(* Logix 5000 project; controller R21 vendor 1 type 14 code 96 rev 21.11; software revision 21.00; part 3 of 5 *)

ADD_ON_INSTRUCTION PSDNP3EventG21V06   (* revision 1.0, vendor ProSoft Technology Inc *)
VAR_IN_OUT
   EventBuffer : PSDNP3MasterEvent[1]; {required}
END_VAR
VAR_INPUT
   BufferSize : DINT; {required}
   CurrentBufferIndex : DINT; {required}
   Reset : BOOL; {required}
   OutstationNodeAddress : INT; {required}
   OutstationIPAddress0 : INT; {required}
   OutstationIPAddress1 : INT; {required}
   OutstationIPAddress2 : INT; {required}
   OutstationIPAddress3 : INT; {required}
END_VAR
VAR_IN_OUT
   DNP3StaticObject : PSDNP3FrozenCounter16WithFlagTime[1]; {required}
END_VAR
VAR_INPUT
   MaxtElementCount : DINT; {required}
END_VAR
VAR_OUTPUT
   EventsProcessed : DINT; {access Read Only, visible}
   LastElementIndex : DINT; {access Read Only, visible}
   LastValue : DINT; {access Read Only, visible}
   LastStatus : SINT; {access Read Only, visible}
   CurrentUnloadIndex : DINT; {access Read Only, visible}
END_VAR
VAR
   UnloadIndex : DINT; {access None}
   EnableInTemp : BOOL; {access None}
   InitialScan : BOOL; {access None}
   EntryValidForProcessing : BOOL; {access None}
   ElementIndex : DINT; {access None}
   NextIndex : DINT; {access None}
   ResetPulse : BOOL; {access None}
   ResetONS : BOOL; {access None}
END_VAR

ROUTINE Logic   (* ladder *)
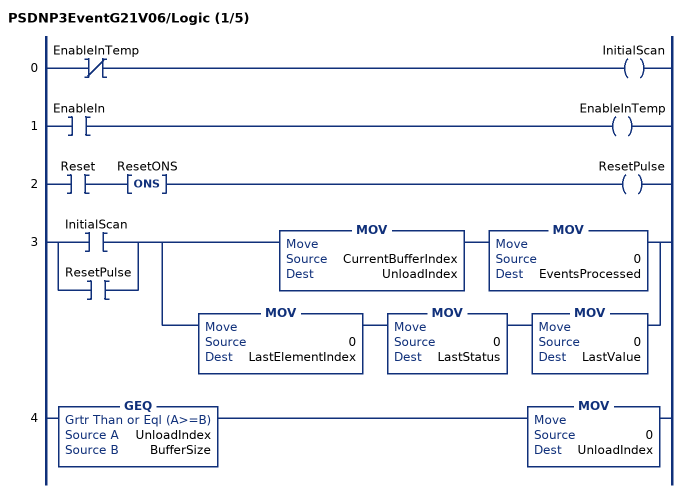
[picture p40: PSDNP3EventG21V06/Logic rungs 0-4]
   0: XIO(EnableInTemp)OTE(InitialScan);
   1: XIC(EnableIn)OTE(EnableInTemp);
   2: XIC(Reset)ONS(ResetONS)OTE(ResetPulse);
   3: [XIC(InitialScan) ,XIC(ResetPulse) ][MOV(CurrentBufferIndex,UnloadIndex) MOV(0,EventsProcessed) ,MOV(0,LastElementIndex) MOV(0,LastStatus) MOV(0,LastValue) ];
   4: GEQ(UnloadIndex,BufferSize)MOV(0,UnloadIndex);
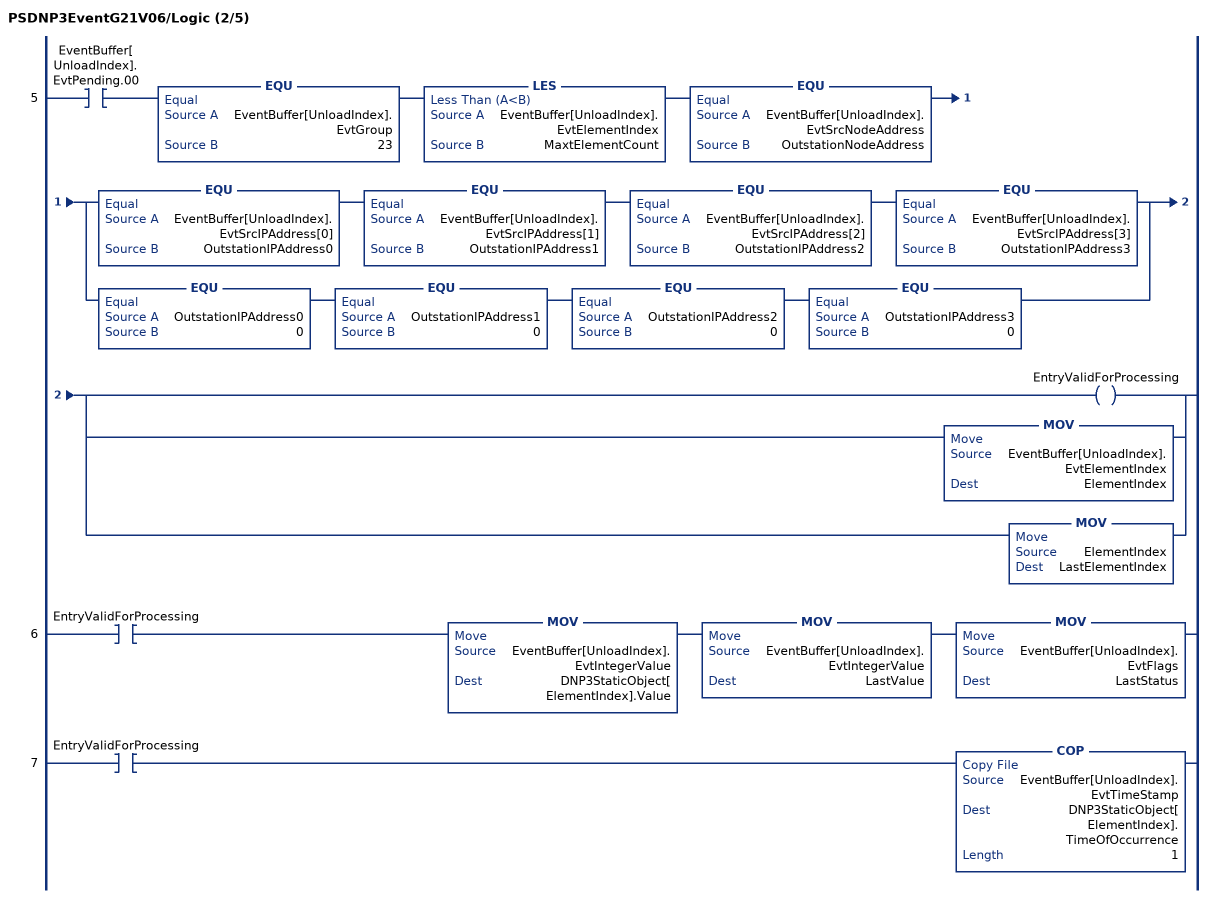
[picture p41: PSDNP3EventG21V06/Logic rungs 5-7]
   5: XIC(EventBuffer[UnloadIndex].EvtPending.00)EQU(EventBuffer[UnloadIndex].EvtGroup,23)LES(EventBuffer[UnloadIndex].EvtElementIndex,MaxtElementCount)EQU(EventBuffer[UnloadIndex].EvtSrcNodeAddress,OutstationNodeAddress)[EQU(EventBuffer[UnloadIndex].EvtSrcIPAddress[0],OutstationIPAddress0) EQU(EventBuffer[UnloadIndex].EvtSrcIPAddress[1],OutstationIPAddress1) EQU(EventBuffer[UnloadIndex].EvtSrcIPAddress[2],OutstationIPAddress2) EQU(EventBuffer[UnloadIndex].EvtSrcIPAddress[3],OutstationIPAddress3) ,EQU(OutstationIPAddress0,0) EQU(OutstationIPAddress1,0) EQU(OutstationIPAddress2,0) EQU(OutstationIPAddress3,0) ][OTE(EntryValidForProcessing) ,MOV(EventBuffer[UnloadIndex].EvtElementIndex,ElementIndex) ,MOV(ElementIndex,LastElementIndex) ];
   6: XIC(EntryValidForProcessing)MOV(EventBuffer[UnloadIndex].EvtIntegerValue,DNP3StaticObject[ElementIndex].Value)MOV(EventBuffer[UnloadIndex].EvtIntegerValue,LastValue)MOV(EventBuffer[UnloadIndex].EvtFlags,LastStatus);
   7: XIC(EntryValidForProcessing)COP(EventBuffer[UnloadIndex].EvtTimeStamp,DNP3StaticObject[ElementIndex].TimeOfOccurrence,1);
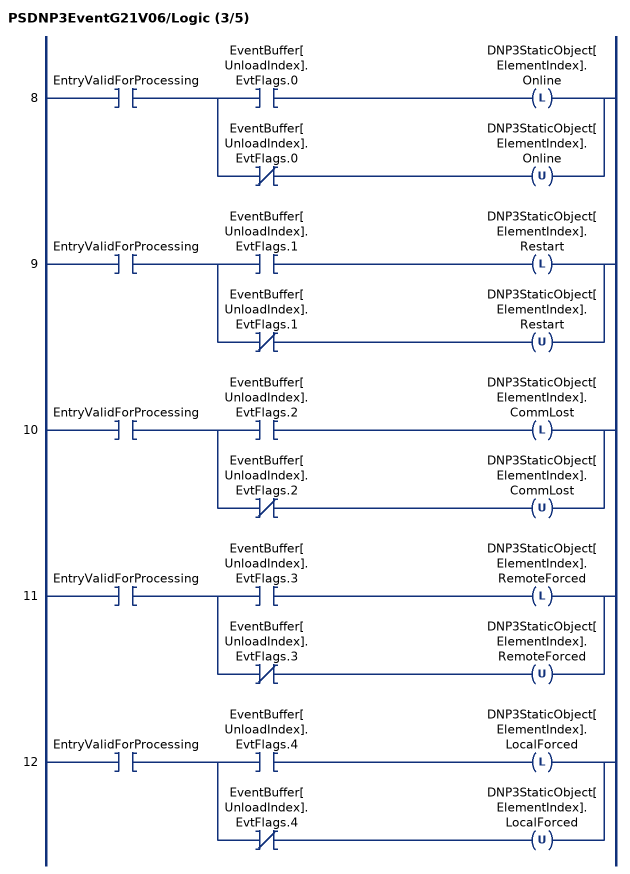
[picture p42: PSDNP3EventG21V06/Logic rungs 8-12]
   8: XIC(EntryValidForProcessing)[XIC(EventBuffer[UnloadIndex].EvtFlags.0) OTL(DNP3StaticObject[ElementIndex].Online) ,XIO(EventBuffer[UnloadIndex].EvtFlags.0) OTU(DNP3StaticObject[ElementIndex].Online) ];
   9: XIC(EntryValidForProcessing)[XIC(EventBuffer[UnloadIndex].EvtFlags.1) OTL(DNP3StaticObject[ElementIndex].Restart) ,XIO(EventBuffer[UnloadIndex].EvtFlags.1) OTU(DNP3StaticObject[ElementIndex].Restart) ];
   10: XIC(EntryValidForProcessing)[XIC(EventBuffer[UnloadIndex].EvtFlags.2) OTL(DNP3StaticObject[ElementIndex].CommLost) ,XIO(EventBuffer[UnloadIndex].EvtFlags.2) OTU(DNP3StaticObject[ElementIndex].CommLost) ];
   11: XIC(EntryValidForProcessing)[XIC(EventBuffer[UnloadIndex].EvtFlags.3) OTL(DNP3StaticObject[ElementIndex].RemoteForced) ,XIO(EventBuffer[UnloadIndex].EvtFlags.3) OTU(DNP3StaticObject[ElementIndex].RemoteForced) ];
   12: XIC(EntryValidForProcessing)[XIC(EventBuffer[UnloadIndex].EvtFlags.4) OTL(DNP3StaticObject[ElementIndex].LocalForced) ,XIO(EventBuffer[UnloadIndex].EvtFlags.4) OTU(DNP3StaticObject[ElementIndex].LocalForced) ];
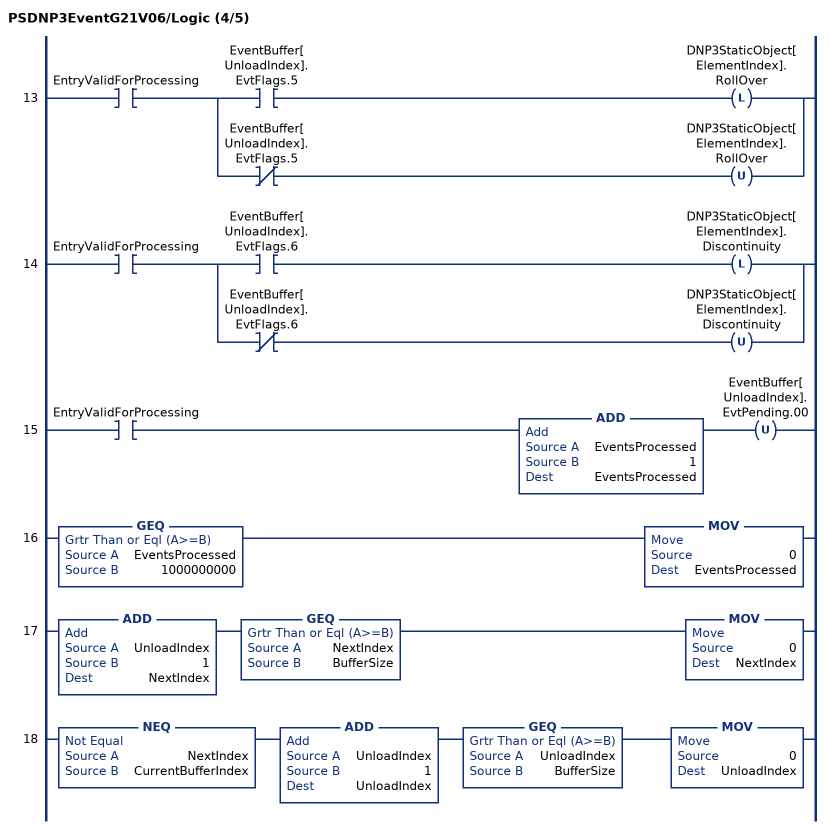
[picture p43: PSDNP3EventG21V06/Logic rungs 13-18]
   13: XIC(EntryValidForProcessing)[XIC(EventBuffer[UnloadIndex].EvtFlags.5) OTL(DNP3StaticObject[ElementIndex].RollOver) ,XIO(EventBuffer[UnloadIndex].EvtFlags.5) OTU(DNP3StaticObject[ElementIndex].RollOver) ];
   14: XIC(EntryValidForProcessing)[XIC(EventBuffer[UnloadIndex].EvtFlags.6) OTL(DNP3StaticObject[ElementIndex].Discontinuity) ,XIO(EventBuffer[UnloadIndex].EvtFlags.6) OTU(DNP3StaticObject[ElementIndex].Discontinuity) ];
   15: XIC(EntryValidForProcessing)ADD(EventsProcessed,1,EventsProcessed)OTU(EventBuffer[UnloadIndex].EvtPending.00);
   16: GEQ(EventsProcessed,1000000000)MOV(0,EventsProcessed);
   17: ADD(UnloadIndex,1,NextIndex)GEQ(NextIndex,BufferSize)MOV(0,NextIndex);
   18: NEQ(NextIndex,CurrentBufferIndex)ADD(UnloadIndex,1,UnloadIndex)GEQ(UnloadIndex,BufferSize)MOV(0,UnloadIndex);
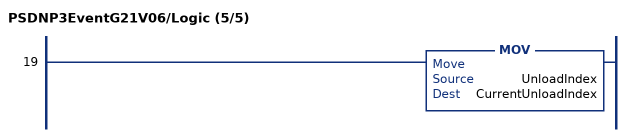
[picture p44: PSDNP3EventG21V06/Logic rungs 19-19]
   19: MOV(UnloadIndex,CurrentUnloadIndex);
END_ROUTINE
END_ADD_ON_INSTRUCTION

ADD_ON_INSTRUCTION PSDNP3EventG21V09   (* revision 1.0, vendor ProSoft Technology Inc *)
VAR_IN_OUT
   EventBuffer : PSDNP3MasterEvent[1]; {required}
END_VAR
VAR_INPUT
   BufferSize : DINT; {required}
   CurrentBufferIndex : DINT; {required}
   Reset : BOOL; {required}
   OutstationNodeAddress : INT; {required}
   OutstationIPAddress0 : INT; {required}
   OutstationIPAddress1 : INT; {required}
   OutstationIPAddress2 : INT; {required}
   OutstationIPAddress3 : INT; {required}
END_VAR
VAR_IN_OUT
   DNP3StaticObject : DINT[1]; {required}
END_VAR
VAR_INPUT
   MaxtElementCount : DINT; {required}
END_VAR
VAR_OUTPUT
   EventsProcessed : DINT; {access Read Only, visible}
   LastElementIndex : DINT; {access Read Only, visible}
   LastValue : DINT; {access Read Only, visible}
   LastStatus : SINT; {access Read Only, visible}
   CurrentUnloadIndex : DINT; {access Read Only, visible}
END_VAR
VAR
   UnloadIndex : DINT; {access None}
   EnableInTemp : BOOL; {access None}
   InitialScan : BOOL; {access None}
   EntryValidForProcessing : BOOL; {access None}
   ElementIndex : DINT; {access None}
   NextIndex : DINT; {access None}
   ResetPulse : BOOL; {access None}
   ResetONS : BOOL; {access None}
END_VAR

ROUTINE Logic   (* ladder *)
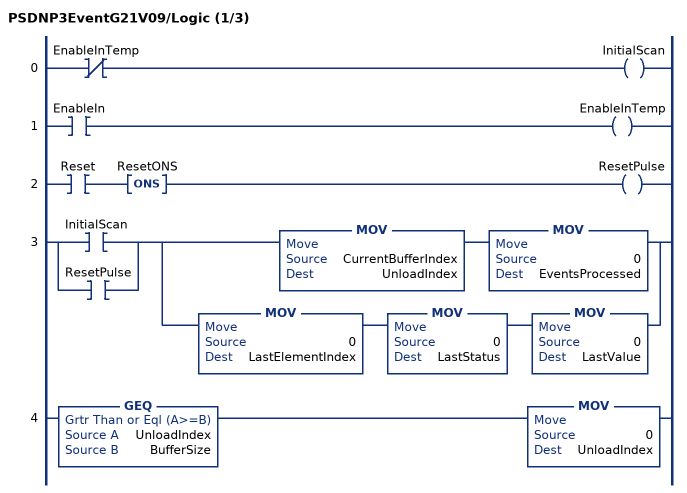
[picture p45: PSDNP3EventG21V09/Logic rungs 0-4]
   0: XIO(EnableInTemp)OTE(InitialScan);
   1: XIC(EnableIn)OTE(EnableInTemp);
   2: XIC(Reset)ONS(ResetONS)OTE(ResetPulse);
   3: [XIC(InitialScan) ,XIC(ResetPulse) ][MOV(CurrentBufferIndex,UnloadIndex) MOV(0,EventsProcessed) ,MOV(0,LastElementIndex) MOV(0,LastStatus) MOV(0,LastValue) ];
   4: GEQ(UnloadIndex,BufferSize)MOV(0,UnloadIndex);
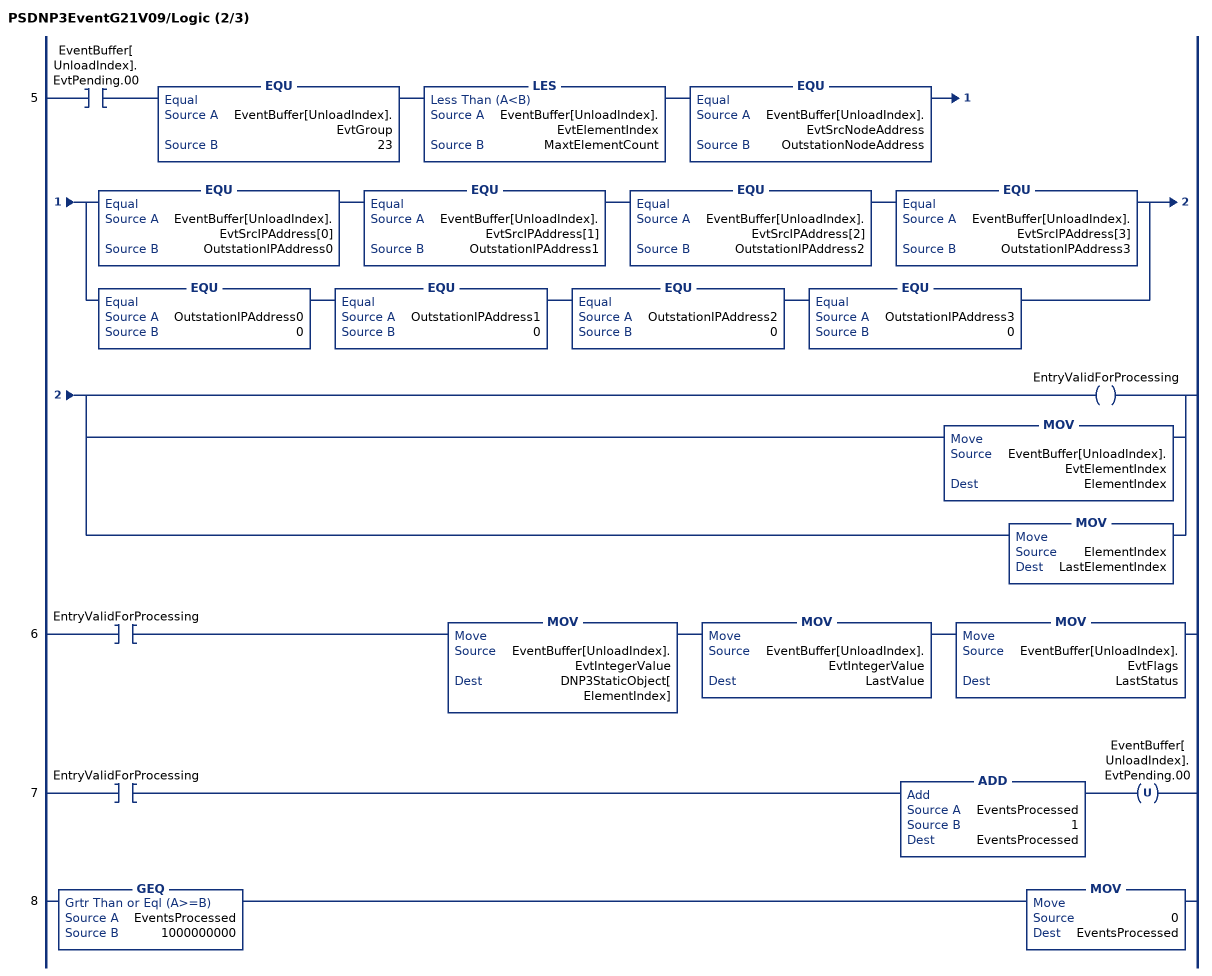
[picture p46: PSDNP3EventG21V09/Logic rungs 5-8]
   5: XIC(EventBuffer[UnloadIndex].EvtPending.00)EQU(EventBuffer[UnloadIndex].EvtGroup,23)LES(EventBuffer[UnloadIndex].EvtElementIndex,MaxtElementCount)EQU(EventBuffer[UnloadIndex].EvtSrcNodeAddress,OutstationNodeAddress)[EQU(EventBuffer[UnloadIndex].EvtSrcIPAddress[0],OutstationIPAddress0) EQU(EventBuffer[UnloadIndex].EvtSrcIPAddress[1],OutstationIPAddress1) EQU(EventBuffer[UnloadIndex].EvtSrcIPAddress[2],OutstationIPAddress2) EQU(EventBuffer[UnloadIndex].EvtSrcIPAddress[3],OutstationIPAddress3) ,EQU(OutstationIPAddress0,0) EQU(OutstationIPAddress1,0) EQU(OutstationIPAddress2,0) EQU(OutstationIPAddress3,0) ][OTE(EntryValidForProcessing) ,MOV(EventBuffer[UnloadIndex].EvtElementIndex,ElementIndex) ,MOV(ElementIndex,LastElementIndex) ];
   6: XIC(EntryValidForProcessing)MOV(EventBuffer[UnloadIndex].EvtIntegerValue,DNP3StaticObject[ElementIndex])MOV(EventBuffer[UnloadIndex].EvtIntegerValue,LastValue)MOV(EventBuffer[UnloadIndex].EvtFlags,LastStatus);
   7: XIC(EntryValidForProcessing)ADD(EventsProcessed,1,EventsProcessed)OTU(EventBuffer[UnloadIndex].EvtPending.00);
   8: GEQ(EventsProcessed,1000000000)MOV(0,EventsProcessed);
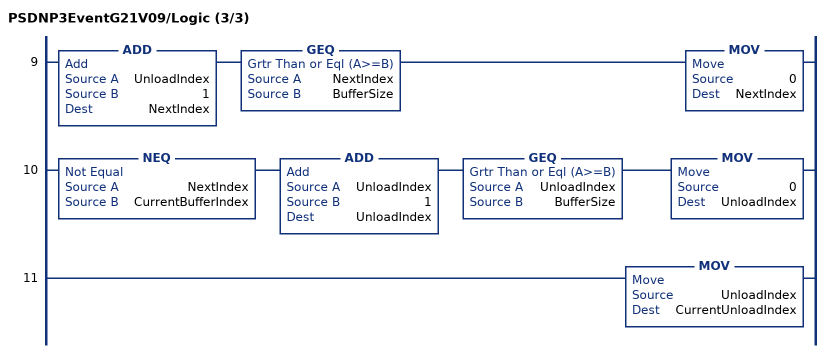
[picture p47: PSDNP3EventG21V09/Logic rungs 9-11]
   9: ADD(UnloadIndex,1,NextIndex)GEQ(NextIndex,BufferSize)MOV(0,NextIndex);
   10: NEQ(NextIndex,CurrentBufferIndex)ADD(UnloadIndex,1,UnloadIndex)GEQ(UnloadIndex,BufferSize)MOV(0,UnloadIndex);
   11: MOV(UnloadIndex,CurrentUnloadIndex);
END_ROUTINE
END_ADD_ON_INSTRUCTION

ADD_ON_INSTRUCTION PSDNP3EventG21V10   (* revision 1.0, vendor ProSoft Technology Inc *)
VAR_IN_OUT
   EventBuffer : PSDNP3MasterEvent[1]; {required}
END_VAR
VAR_INPUT
   BufferSize : DINT; {required}
   CurrentBufferIndex : DINT; {required}
   Reset : BOOL; {required}
   OutstationNodeAddress : INT; {required}
   OutstationIPAddress0 : INT; {required}
   OutstationIPAddress1 : INT; {required}
   OutstationIPAddress2 : INT; {required}
   OutstationIPAddress3 : INT; {required}
END_VAR
VAR_IN_OUT
   DNP3StaticObject : INT[1]; {required}
END_VAR
VAR_INPUT
   MaxtElementCount : DINT; {required}
END_VAR
VAR_OUTPUT
   EventsProcessed : DINT; {access Read Only, visible}
   LastElementIndex : DINT; {access Read Only, visible}
   LastValue : DINT; {access Read Only, visible}
   LastStatus : SINT; {access Read Only, visible}
   CurrentUnloadIndex : DINT; {access Read Only, visible}
END_VAR
VAR
   UnloadIndex : DINT; {access None}
   EnableInTemp : BOOL; {access None}
   InitialScan : BOOL; {access None}
   EntryValidForProcessing : BOOL; {access None}
   ElementIndex : DINT; {access None}
   NextIndex : DINT; {access None}
   ResetPulse : BOOL; {access None}
   ResetONS : BOOL; {access None}
END_VAR

ROUTINE Logic   (* ladder *)
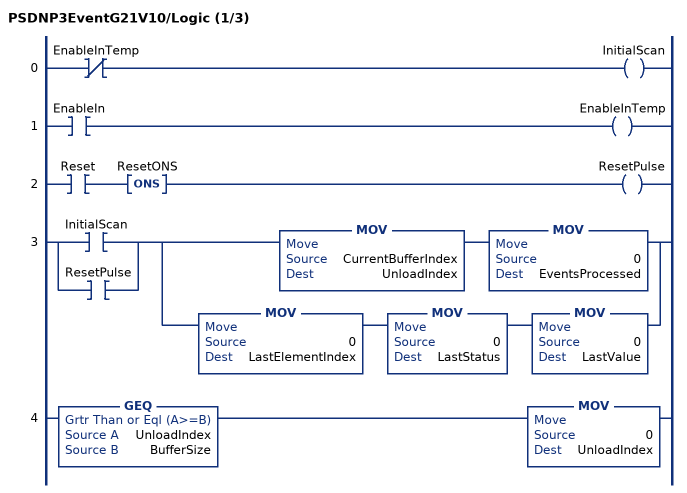
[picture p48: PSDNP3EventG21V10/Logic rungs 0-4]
   0: XIO(EnableInTemp)OTE(InitialScan);
   1: XIC(EnableIn)OTE(EnableInTemp);
   2: XIC(Reset)ONS(ResetONS)OTE(ResetPulse);
   3: [XIC(InitialScan) ,XIC(ResetPulse) ][MOV(CurrentBufferIndex,UnloadIndex) MOV(0,EventsProcessed) ,MOV(0,LastElementIndex) MOV(0,LastStatus) MOV(0,LastValue) ];
   4: GEQ(UnloadIndex,BufferSize)MOV(0,UnloadIndex);
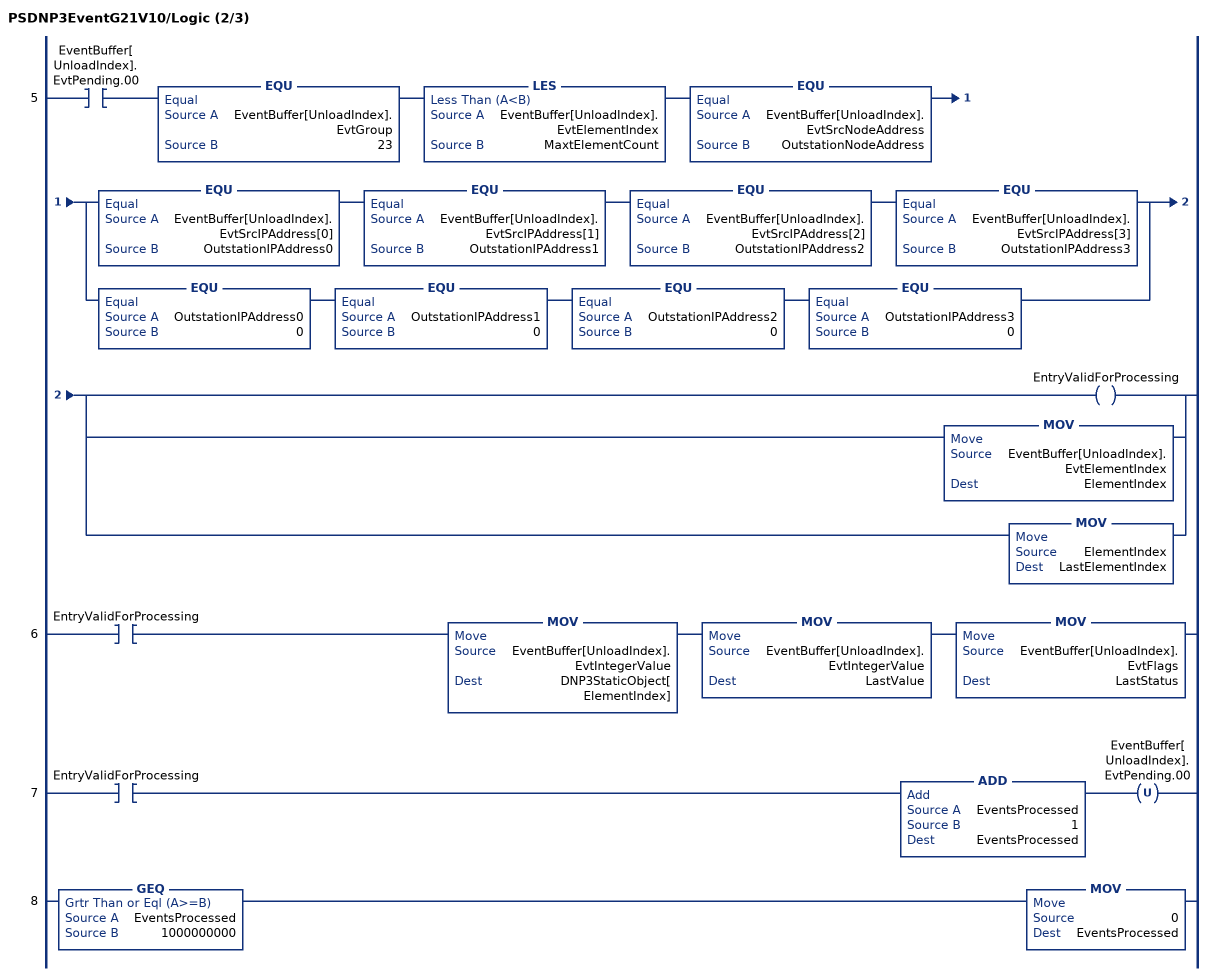
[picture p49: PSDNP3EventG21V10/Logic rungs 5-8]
   5: XIC(EventBuffer[UnloadIndex].EvtPending.00)EQU(EventBuffer[UnloadIndex].EvtGroup,23)LES(EventBuffer[UnloadIndex].EvtElementIndex,MaxtElementCount)EQU(EventBuffer[UnloadIndex].EvtSrcNodeAddress,OutstationNodeAddress)[EQU(EventBuffer[UnloadIndex].EvtSrcIPAddress[0],OutstationIPAddress0) EQU(EventBuffer[UnloadIndex].EvtSrcIPAddress[1],OutstationIPAddress1) EQU(EventBuffer[UnloadIndex].EvtSrcIPAddress[2],OutstationIPAddress2) EQU(EventBuffer[UnloadIndex].EvtSrcIPAddress[3],OutstationIPAddress3) ,EQU(OutstationIPAddress0,0) EQU(OutstationIPAddress1,0) EQU(OutstationIPAddress2,0) EQU(OutstationIPAddress3,0) ][OTE(EntryValidForProcessing) ,MOV(EventBuffer[UnloadIndex].EvtElementIndex,ElementIndex) ,MOV(ElementIndex,LastElementIndex) ];
   6: XIC(EntryValidForProcessing)MOV(EventBuffer[UnloadIndex].EvtIntegerValue,DNP3StaticObject[ElementIndex])MOV(EventBuffer[UnloadIndex].EvtIntegerValue,LastValue)MOV(EventBuffer[UnloadIndex].EvtFlags,LastStatus);
   7: XIC(EntryValidForProcessing)ADD(EventsProcessed,1,EventsProcessed)OTU(EventBuffer[UnloadIndex].EvtPending.00);
   8: GEQ(EventsProcessed,1000000000)MOV(0,EventsProcessed);
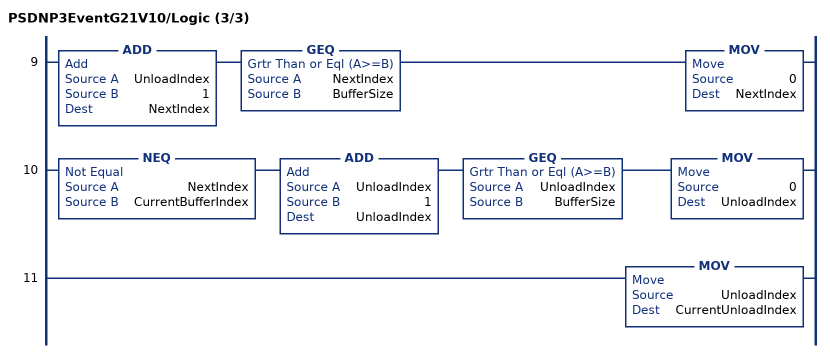
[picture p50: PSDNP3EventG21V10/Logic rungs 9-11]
   9: ADD(UnloadIndex,1,NextIndex)GEQ(NextIndex,BufferSize)MOV(0,NextIndex);
   10: NEQ(NextIndex,CurrentBufferIndex)ADD(UnloadIndex,1,UnloadIndex)GEQ(UnloadIndex,BufferSize)MOV(0,UnloadIndex);
   11: MOV(UnloadIndex,CurrentUnloadIndex);
END_ROUTINE
END_ADD_ON_INSTRUCTION

ADD_ON_INSTRUCTION PSDNP3EventG30V01   (* revision 1.0, vendor ProSoft Technology Inc *)
VAR_IN_OUT
   EventBuffer : PSDNP3MasterEvent[1]; {required}
END_VAR
VAR_INPUT
   BufferSize : DINT; {required}
   CurrentBufferIndex : DINT; {required}
   Reset : BOOL; {required}
   OutstationNodeAddress : INT; {required}
   OutstationIPAddress0 : INT; {required}
   OutstationIPAddress1 : INT; {required}
   OutstationIPAddress2 : INT; {required}
   OutstationIPAddress3 : INT; {required}
END_VAR
VAR_IN_OUT
   DNP3StaticObject : PSDNP3AnalogInput32Flag[1]; {required}
END_VAR
VAR_INPUT
   MaxtElementCount : DINT; {required}
END_VAR
VAR_OUTPUT
   EventsProcessed : DINT; {access Read Only, visible}
   LastElementIndex : DINT; {access Read Only, visible}
   LastValue : DINT; {access Read Only, visible}
   LastStatus : SINT; {access Read Only, visible}
   CurrentUnloadIndex : DINT; {access Read Only, visible}
END_VAR
VAR
   UnloadIndex : DINT; {access None}
   EnableInTemp : BOOL; {access None}
   InitialScan : BOOL; {access None}
   EntryValidForProcessing : BOOL; {access None}
   ElementIndex : DINT; {access None}
   NextIndex : DINT; {access None}
   ResetPulse : BOOL; {access None}
   ResetONS : BOOL; {access None}
END_VAR

ROUTINE Logic   (* ladder *)
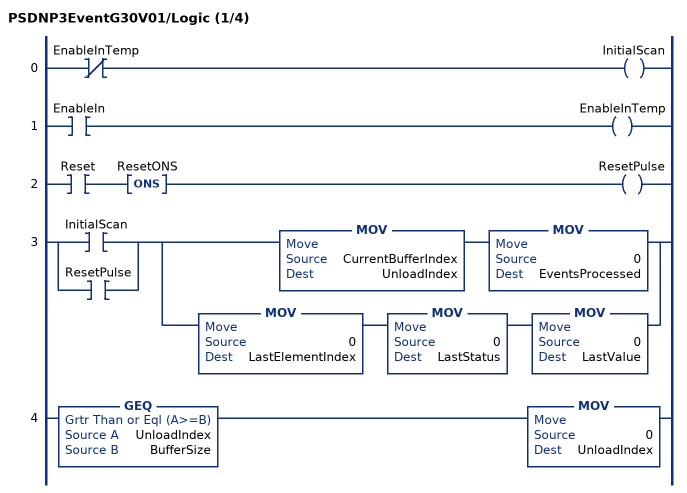
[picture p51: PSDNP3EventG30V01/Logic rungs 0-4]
   0: XIO(EnableInTemp)OTE(InitialScan);
   1: XIC(EnableIn)OTE(EnableInTemp);
   2: XIC(Reset)ONS(ResetONS)OTE(ResetPulse);
   3: [XIC(InitialScan) ,XIC(ResetPulse) ][MOV(CurrentBufferIndex,UnloadIndex) MOV(0,EventsProcessed) ,MOV(0,LastElementIndex) MOV(0,LastStatus) MOV(0,LastValue) ];
   4: GEQ(UnloadIndex,BufferSize)MOV(0,UnloadIndex);
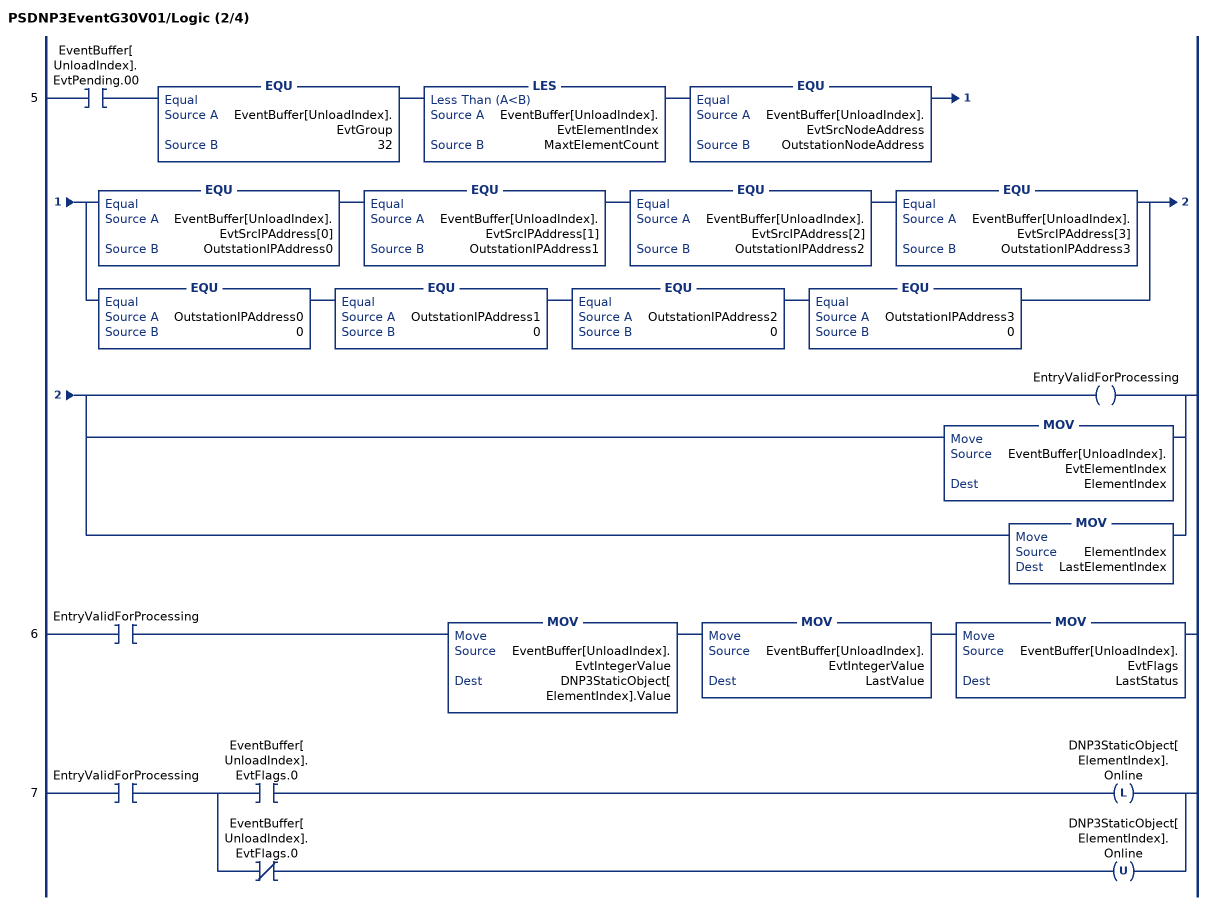
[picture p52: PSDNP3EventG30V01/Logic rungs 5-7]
   5: XIC(EventBuffer[UnloadIndex].EvtPending.00)EQU(EventBuffer[UnloadIndex].EvtGroup,32)LES(EventBuffer[UnloadIndex].EvtElementIndex,MaxtElementCount)EQU(EventBuffer[UnloadIndex].EvtSrcNodeAddress,OutstationNodeAddress)[EQU(EventBuffer[UnloadIndex].EvtSrcIPAddress[0],OutstationIPAddress0) EQU(EventBuffer[UnloadIndex].EvtSrcIPAddress[1],OutstationIPAddress1) EQU(EventBuffer[UnloadIndex].EvtSrcIPAddress[2],OutstationIPAddress2) EQU(EventBuffer[UnloadIndex].EvtSrcIPAddress[3],OutstationIPAddress3) ,EQU(OutstationIPAddress0,0) EQU(OutstationIPAddress1,0) EQU(OutstationIPAddress2,0) EQU(OutstationIPAddress3,0) ][OTE(EntryValidForProcessing) ,MOV(EventBuffer[UnloadIndex].EvtElementIndex,ElementIndex) ,MOV(ElementIndex,LastElementIndex) ];
   6: XIC(EntryValidForProcessing)MOV(EventBuffer[UnloadIndex].EvtIntegerValue,DNP3StaticObject[ElementIndex].Value)MOV(EventBuffer[UnloadIndex].EvtIntegerValue,LastValue)MOV(EventBuffer[UnloadIndex].EvtFlags,LastStatus);
   7: XIC(EntryValidForProcessing)[XIC(EventBuffer[UnloadIndex].EvtFlags.0) OTL(DNP3StaticObject[ElementIndex].Online) ,XIO(EventBuffer[UnloadIndex].EvtFlags.0) OTU(DNP3StaticObject[ElementIndex].Online) ];
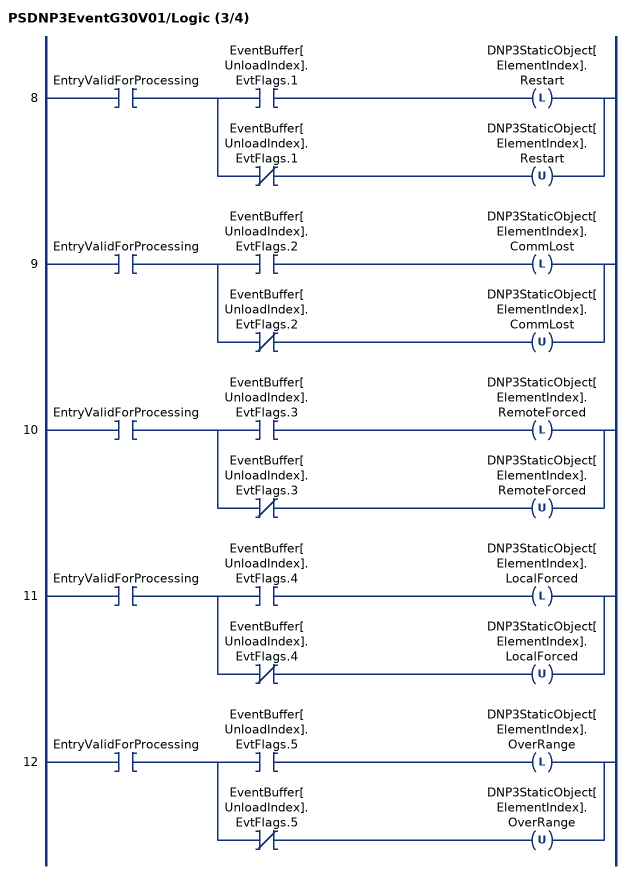
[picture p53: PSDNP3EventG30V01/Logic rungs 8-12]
   8: XIC(EntryValidForProcessing)[XIC(EventBuffer[UnloadIndex].EvtFlags.1) OTL(DNP3StaticObject[ElementIndex].Restart) ,XIO(EventBuffer[UnloadIndex].EvtFlags.1) OTU(DNP3StaticObject[ElementIndex].Restart) ];
   9: XIC(EntryValidForProcessing)[XIC(EventBuffer[UnloadIndex].EvtFlags.2) OTL(DNP3StaticObject[ElementIndex].CommLost) ,XIO(EventBuffer[UnloadIndex].EvtFlags.2) OTU(DNP3StaticObject[ElementIndex].CommLost) ];
   10: XIC(EntryValidForProcessing)[XIC(EventBuffer[UnloadIndex].EvtFlags.3) OTL(DNP3StaticObject[ElementIndex].RemoteForced) ,XIO(EventBuffer[UnloadIndex].EvtFlags.3) OTU(DNP3StaticObject[ElementIndex].RemoteForced) ];
   11: XIC(EntryValidForProcessing)[XIC(EventBuffer[UnloadIndex].EvtFlags.4) OTL(DNP3StaticObject[ElementIndex].LocalForced) ,XIO(EventBuffer[UnloadIndex].EvtFlags.4) OTU(DNP3StaticObject[ElementIndex].LocalForced) ];
   12: XIC(EntryValidForProcessing)[XIC(EventBuffer[UnloadIndex].EvtFlags.5) OTL(DNP3StaticObject[ElementIndex].OverRange) ,XIO(EventBuffer[UnloadIndex].EvtFlags.5) OTU(DNP3StaticObject[ElementIndex].OverRange) ];
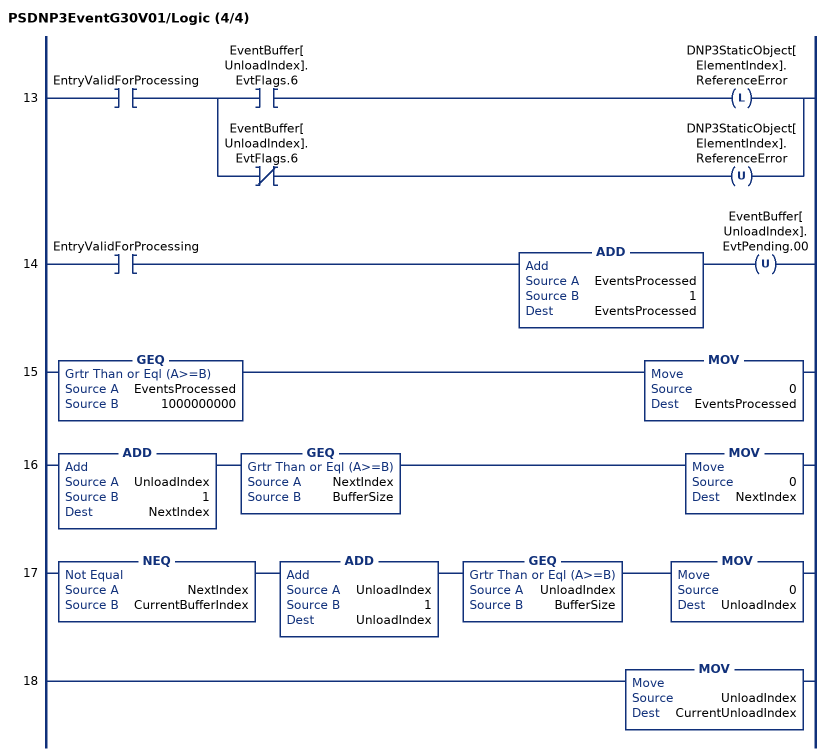
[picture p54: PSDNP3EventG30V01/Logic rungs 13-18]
   13: XIC(EntryValidForProcessing)[XIC(EventBuffer[UnloadIndex].EvtFlags.6) OTL(DNP3StaticObject[ElementIndex].ReferenceError) ,XIO(EventBuffer[UnloadIndex].EvtFlags.6) OTU(DNP3StaticObject[ElementIndex].ReferenceError) ];
   14: XIC(EntryValidForProcessing)ADD(EventsProcessed,1,EventsProcessed)OTU(EventBuffer[UnloadIndex].EvtPending.00);
   15: GEQ(EventsProcessed,1000000000)MOV(0,EventsProcessed);
   16: ADD(UnloadIndex,1,NextIndex)GEQ(NextIndex,BufferSize)MOV(0,NextIndex);
   17: NEQ(NextIndex,CurrentBufferIndex)ADD(UnloadIndex,1,UnloadIndex)GEQ(UnloadIndex,BufferSize)MOV(0,UnloadIndex);
   18: MOV(UnloadIndex,CurrentUnloadIndex);
END_ROUTINE
END_ADD_ON_INSTRUCTION

ADD_ON_INSTRUCTION PSDNP3EventG30V02   (* revision 1.0, vendor ProSoft Technology Inc *)
VAR_IN_OUT
   EventBuffer : PSDNP3MasterEvent[1]; {required}
END_VAR
VAR_INPUT
   BufferSize : DINT; {required}
   CurrentBufferIndex : DINT; {required}
   Reset : BOOL; {required}
   OutstationNodeAddress : INT; {required}
   OutstationIPAddress0 : INT; {required}
   OutstationIPAddress1 : INT; {required}
   OutstationIPAddress2 : INT; {required}
   OutstationIPAddress3 : INT; {required}
END_VAR
VAR_IN_OUT
   DNP3StaticObject : PSDNP3AnalogInput16Flag[1]; {required}
END_VAR
VAR_INPUT
   MaxtElementCount : DINT; {required}
END_VAR
VAR_OUTPUT
   EventsProcessed : DINT; {access Read Only, visible}
   LastElementIndex : DINT; {access Read Only, visible}
   LastValue : DINT; {access Read Only, visible}
   LastStatus : SINT; {access Read Only, visible}
   CurrentUnloadIndex : DINT; {access Read Only, visible}
END_VAR
VAR
   UnloadIndex : DINT; {access None}
   EnableInTemp : BOOL; {access None}
   InitialScan : BOOL; {access None}
   EntryValidForProcessing : BOOL; {access None}
   ElementIndex : DINT; {access None}
   NextIndex : DINT; {access None}
   ResetPulse : BOOL; {access None}
   ResetONS : BOOL; {access None}
END_VAR

ROUTINE Logic   (* ladder *)
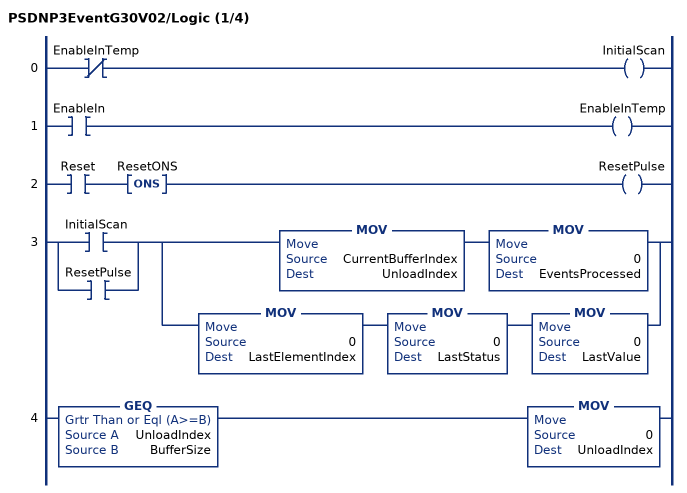
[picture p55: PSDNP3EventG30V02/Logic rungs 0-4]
   0: XIO(EnableInTemp)OTE(InitialScan);
   1: XIC(EnableIn)OTE(EnableInTemp);
   2: XIC(Reset)ONS(ResetONS)OTE(ResetPulse);
   3: [XIC(InitialScan) ,XIC(ResetPulse) ][MOV(CurrentBufferIndex,UnloadIndex) MOV(0,EventsProcessed) ,MOV(0,LastElementIndex) MOV(0,LastStatus) MOV(0,LastValue) ];
   4: GEQ(UnloadIndex,BufferSize)MOV(0,UnloadIndex);
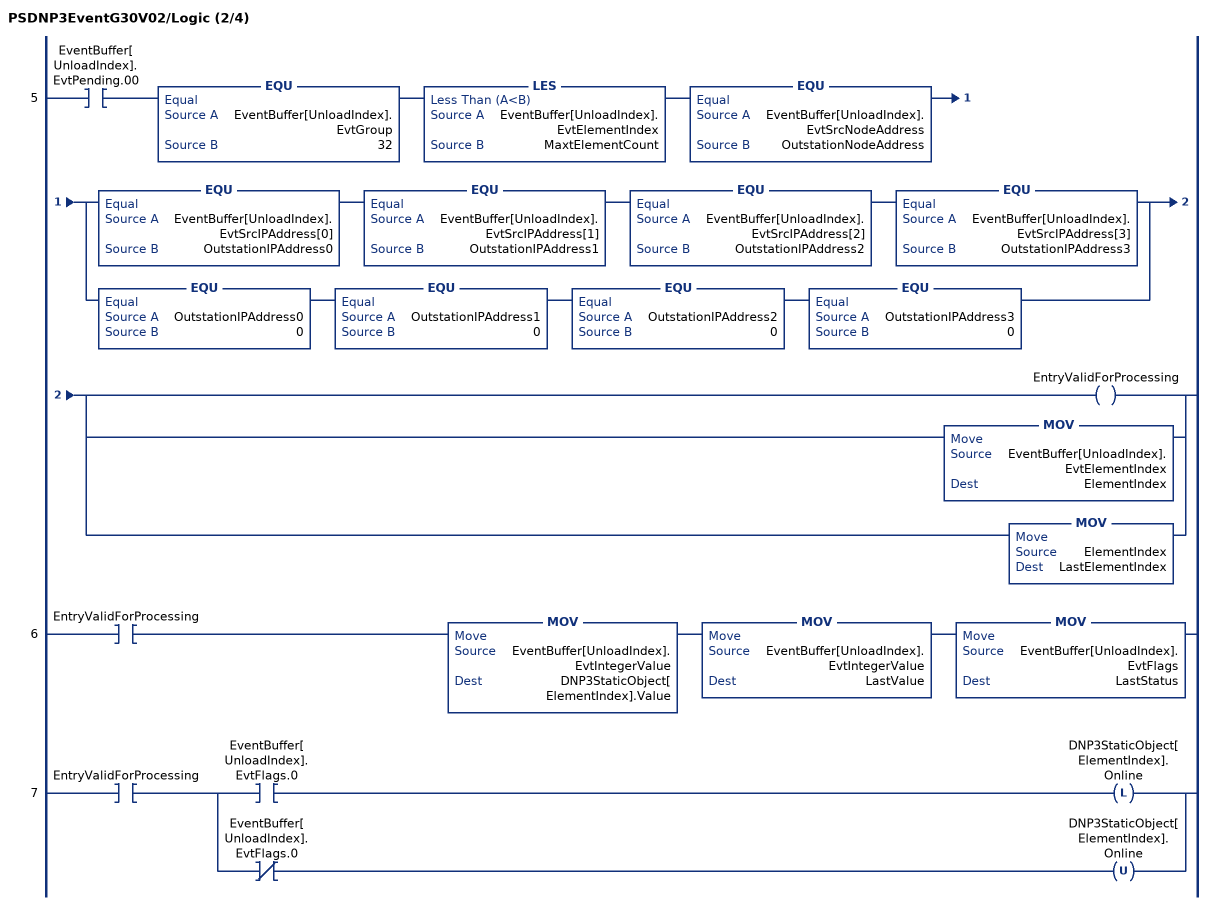
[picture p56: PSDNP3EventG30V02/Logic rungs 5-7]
   5: XIC(EventBuffer[UnloadIndex].EvtPending.00)EQU(EventBuffer[UnloadIndex].EvtGroup,32)LES(EventBuffer[UnloadIndex].EvtElementIndex,MaxtElementCount)EQU(EventBuffer[UnloadIndex].EvtSrcNodeAddress,OutstationNodeAddress)[EQU(EventBuffer[UnloadIndex].EvtSrcIPAddress[0],OutstationIPAddress0) EQU(EventBuffer[UnloadIndex].EvtSrcIPAddress[1],OutstationIPAddress1) EQU(EventBuffer[UnloadIndex].EvtSrcIPAddress[2],OutstationIPAddress2) EQU(EventBuffer[UnloadIndex].EvtSrcIPAddress[3],OutstationIPAddress3) ,EQU(OutstationIPAddress0,0) EQU(OutstationIPAddress1,0) EQU(OutstationIPAddress2,0) EQU(OutstationIPAddress3,0) ][OTE(EntryValidForProcessing) ,MOV(EventBuffer[UnloadIndex].EvtElementIndex,ElementIndex) ,MOV(ElementIndex,LastElementIndex) ];
   6: XIC(EntryValidForProcessing)MOV(EventBuffer[UnloadIndex].EvtIntegerValue,DNP3StaticObject[ElementIndex].Value)MOV(EventBuffer[UnloadIndex].EvtIntegerValue,LastValue)MOV(EventBuffer[UnloadIndex].EvtFlags,LastStatus);
   7: XIC(EntryValidForProcessing)[XIC(EventBuffer[UnloadIndex].EvtFlags.0) OTL(DNP3StaticObject[ElementIndex].Online) ,XIO(EventBuffer[UnloadIndex].EvtFlags.0) OTU(DNP3StaticObject[ElementIndex].Online) ];
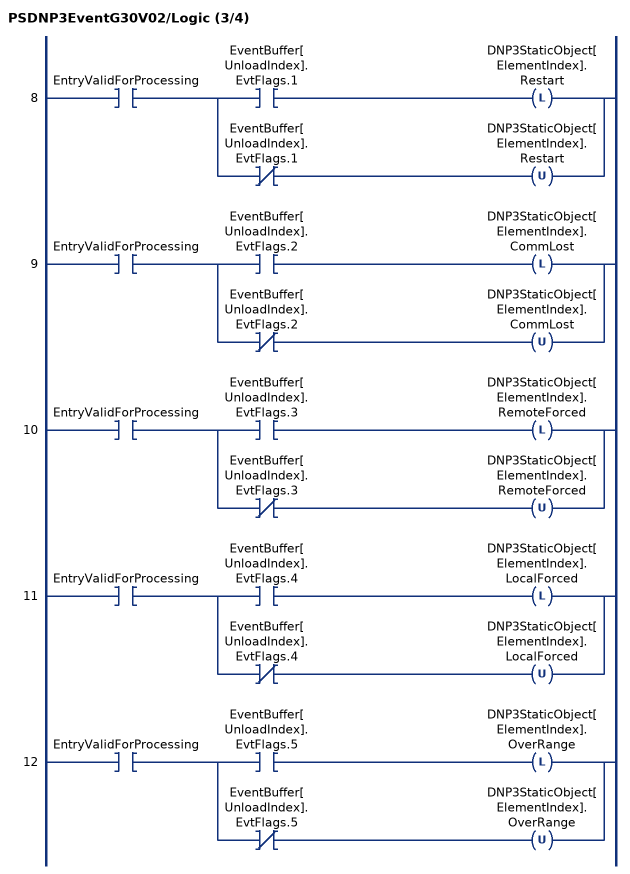
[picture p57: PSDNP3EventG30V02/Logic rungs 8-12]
   8: XIC(EntryValidForProcessing)[XIC(EventBuffer[UnloadIndex].EvtFlags.1) OTL(DNP3StaticObject[ElementIndex].Restart) ,XIO(EventBuffer[UnloadIndex].EvtFlags.1) OTU(DNP3StaticObject[ElementIndex].Restart) ];
   9: XIC(EntryValidForProcessing)[XIC(EventBuffer[UnloadIndex].EvtFlags.2) OTL(DNP3StaticObject[ElementIndex].CommLost) ,XIO(EventBuffer[UnloadIndex].EvtFlags.2) OTU(DNP3StaticObject[ElementIndex].CommLost) ];
   10: XIC(EntryValidForProcessing)[XIC(EventBuffer[UnloadIndex].EvtFlags.3) OTL(DNP3StaticObject[ElementIndex].RemoteForced) ,XIO(EventBuffer[UnloadIndex].EvtFlags.3) OTU(DNP3StaticObject[ElementIndex].RemoteForced) ];
   11: XIC(EntryValidForProcessing)[XIC(EventBuffer[UnloadIndex].EvtFlags.4) OTL(DNP3StaticObject[ElementIndex].LocalForced) ,XIO(EventBuffer[UnloadIndex].EvtFlags.4) OTU(DNP3StaticObject[ElementIndex].LocalForced) ];
   12: XIC(EntryValidForProcessing)[XIC(EventBuffer[UnloadIndex].EvtFlags.5) OTL(DNP3StaticObject[ElementIndex].OverRange) ,XIO(EventBuffer[UnloadIndex].EvtFlags.5) OTU(DNP3StaticObject[ElementIndex].OverRange) ];
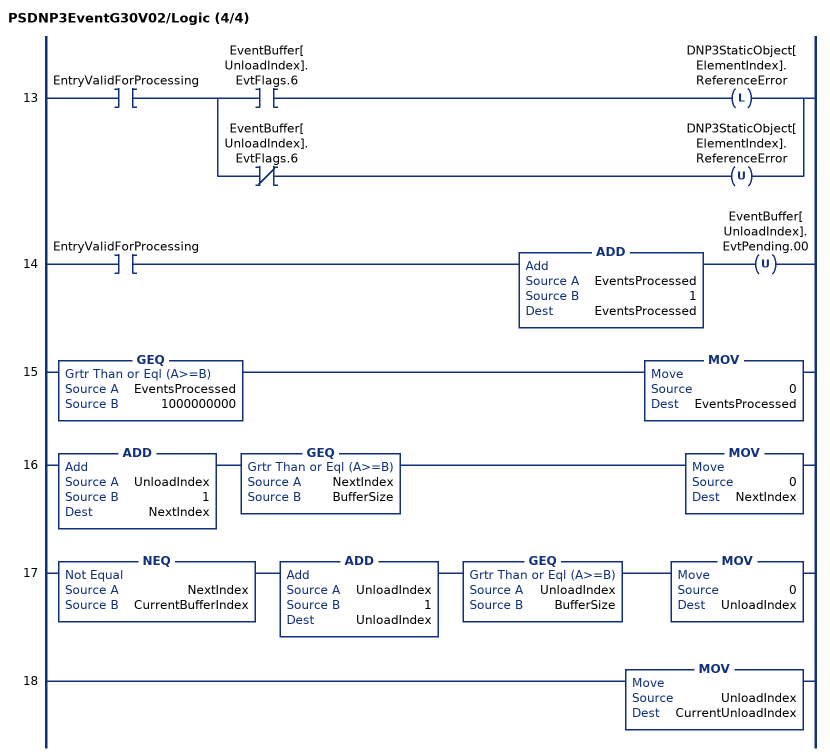
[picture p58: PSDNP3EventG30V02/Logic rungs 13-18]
   13: XIC(EntryValidForProcessing)[XIC(EventBuffer[UnloadIndex].EvtFlags.6) OTL(DNP3StaticObject[ElementIndex].ReferenceError) ,XIO(EventBuffer[UnloadIndex].EvtFlags.6) OTU(DNP3StaticObject[ElementIndex].ReferenceError) ];
   14: XIC(EntryValidForProcessing)ADD(EventsProcessed,1,EventsProcessed)OTU(EventBuffer[UnloadIndex].EvtPending.00);
   15: GEQ(EventsProcessed,1000000000)MOV(0,EventsProcessed);
   16: ADD(UnloadIndex,1,NextIndex)GEQ(NextIndex,BufferSize)MOV(0,NextIndex);
   17: NEQ(NextIndex,CurrentBufferIndex)ADD(UnloadIndex,1,UnloadIndex)GEQ(UnloadIndex,BufferSize)MOV(0,UnloadIndex);
   18: MOV(UnloadIndex,CurrentUnloadIndex);
END_ROUTINE
END_ADD_ON_INSTRUCTION
